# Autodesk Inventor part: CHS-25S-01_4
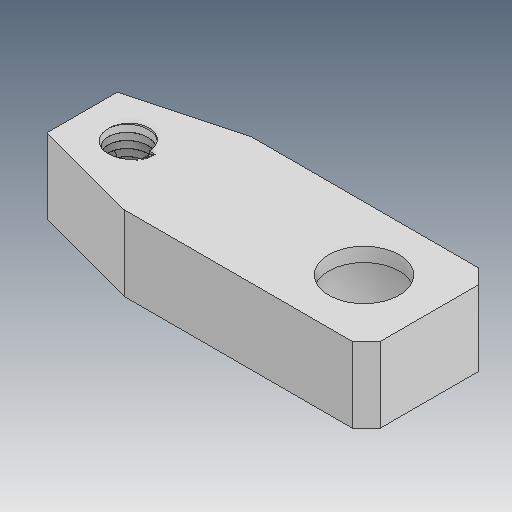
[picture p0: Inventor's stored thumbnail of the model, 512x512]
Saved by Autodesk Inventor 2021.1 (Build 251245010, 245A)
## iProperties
Created: 2019-04
Part Number: CHS-25S-01_4
Material: Ogólny
Document SubType Name: Modeling
Designer: user
Density: 1 g/cm^3
Appearance: Domyślna
Author: user
Revision Number: ÈÎºÎ
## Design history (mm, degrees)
feature "ÊäÈë1"
node "Bryła1"
